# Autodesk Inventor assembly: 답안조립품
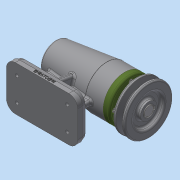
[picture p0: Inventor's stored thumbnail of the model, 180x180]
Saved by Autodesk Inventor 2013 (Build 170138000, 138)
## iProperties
Created: 2017-01
Part Number: 답안조립품
Document SubType Name: Assembly
Designer: dgall
Author: dgall
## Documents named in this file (11)
- C:\Users\dgall\Desktop\470107V1003\답안조립품.iam
- C:\Users\dgall\Desktop\470107V1003\본체.ipt
- C:\Users\dgall\Desktop\470107V1003\축.ipt
- C:\Users\dgall\Desktop\470107V1003\키 5 x 5 x 16.ipt
- C:\Users\dgall\Desktop\470107V1003\베어링 6004.ipt
- C:\Users\dgall\Desktop\470107V1003\베어링 51202.ipt
- C:\Users\dgall\Desktop\470107V1003\어댑터슬리브.ipt
- C:\Users\dgall\Desktop\470107V1003\볼트 M4 x 12.ipt
- C:\Users\dgall\Desktop\470107V1003\커버.ipt
- C:\Users\dgall\Desktop\470107V1003\V벨트풀리.ipt
- C:\Users\dgall\Desktop\470107V1003\멈춤나사 M3x8.ipt
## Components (6 placed, 2 different names)
1. ISO 4762 M4 x 12:1
2. V벨트풀리:1
3. ISO 4762 M4 x 12:2
4. ISO 4762 M4 x 12:3
5. ISO 4762 M4 x 12:4
6. ISO 4762 M4 x 12:5
